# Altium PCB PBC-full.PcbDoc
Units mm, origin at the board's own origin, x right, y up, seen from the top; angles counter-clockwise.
Board outline 80.01 x 65.41 mm, 2 copper layers (Top Layer, Bottom Layer); 75 components, 86 nets, 316 pads, 108 vias.
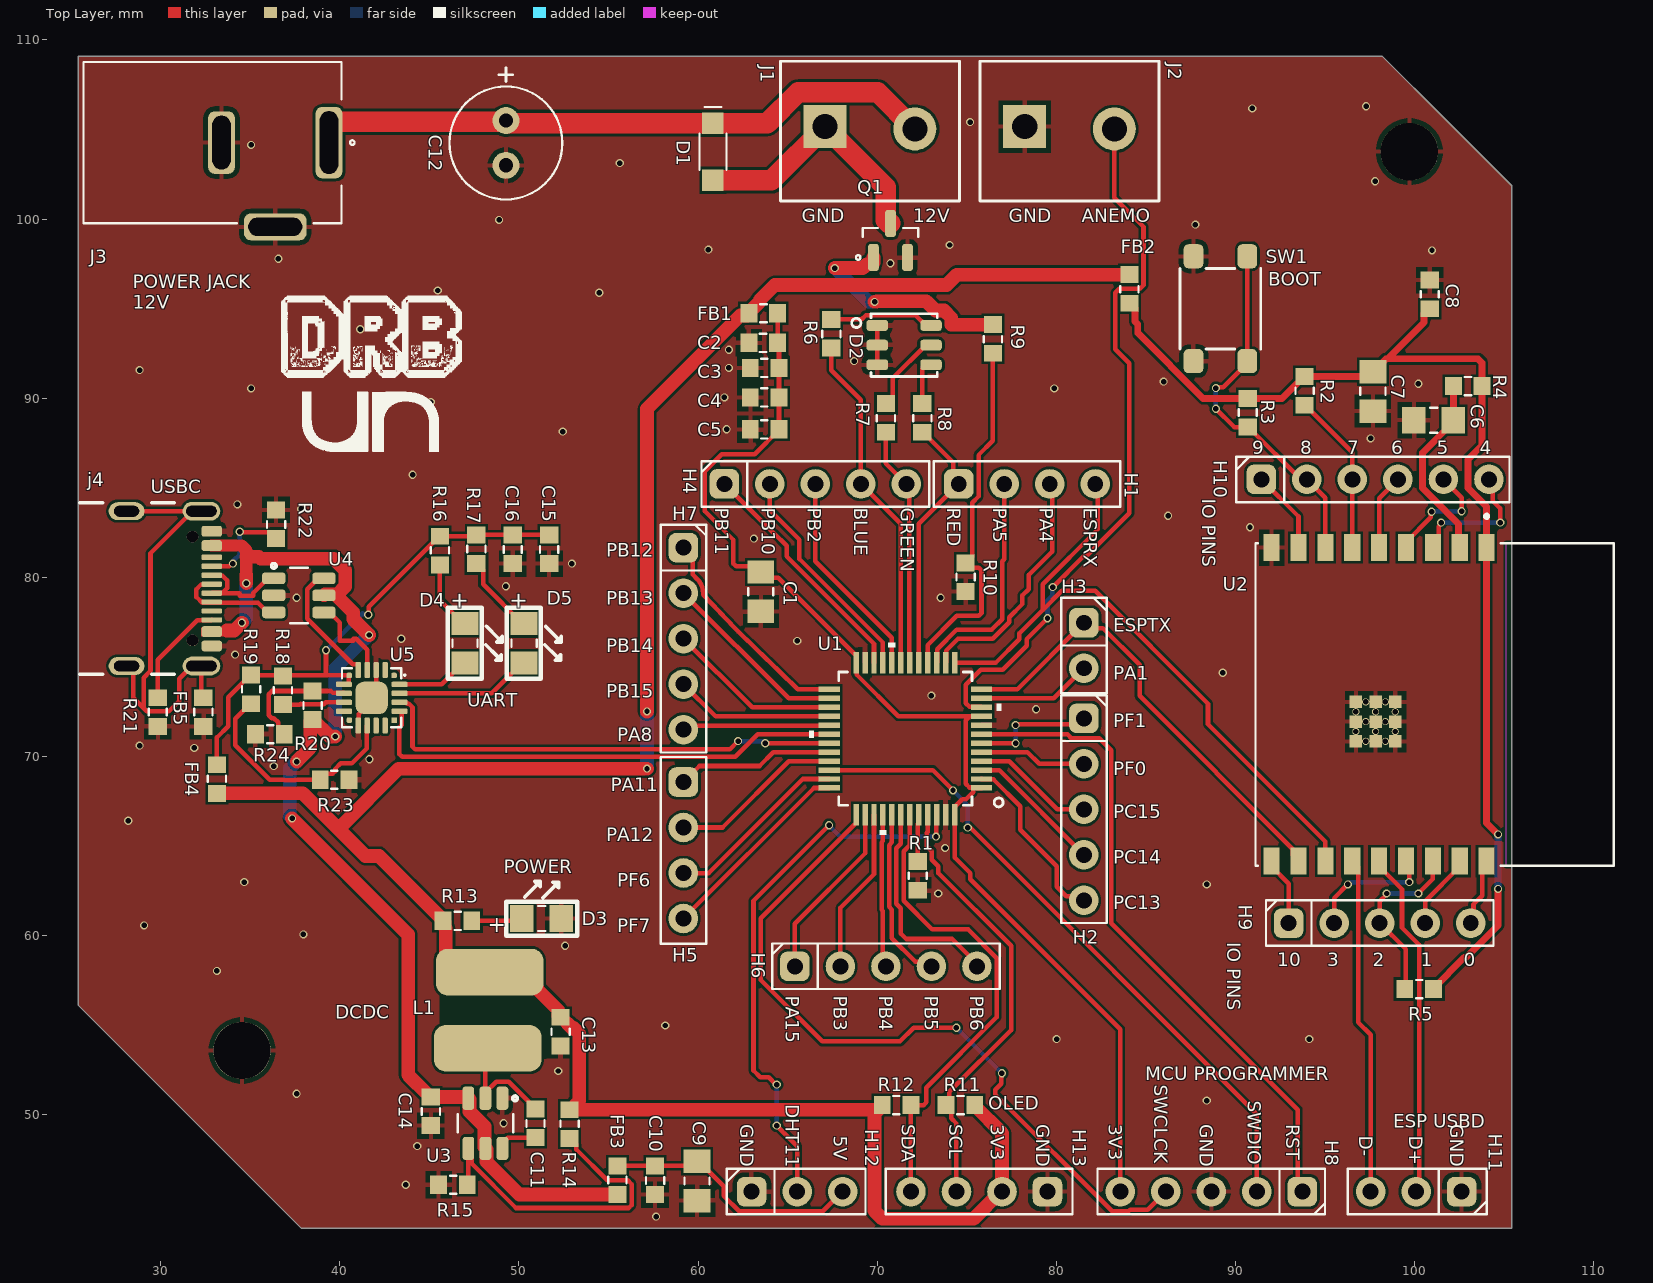
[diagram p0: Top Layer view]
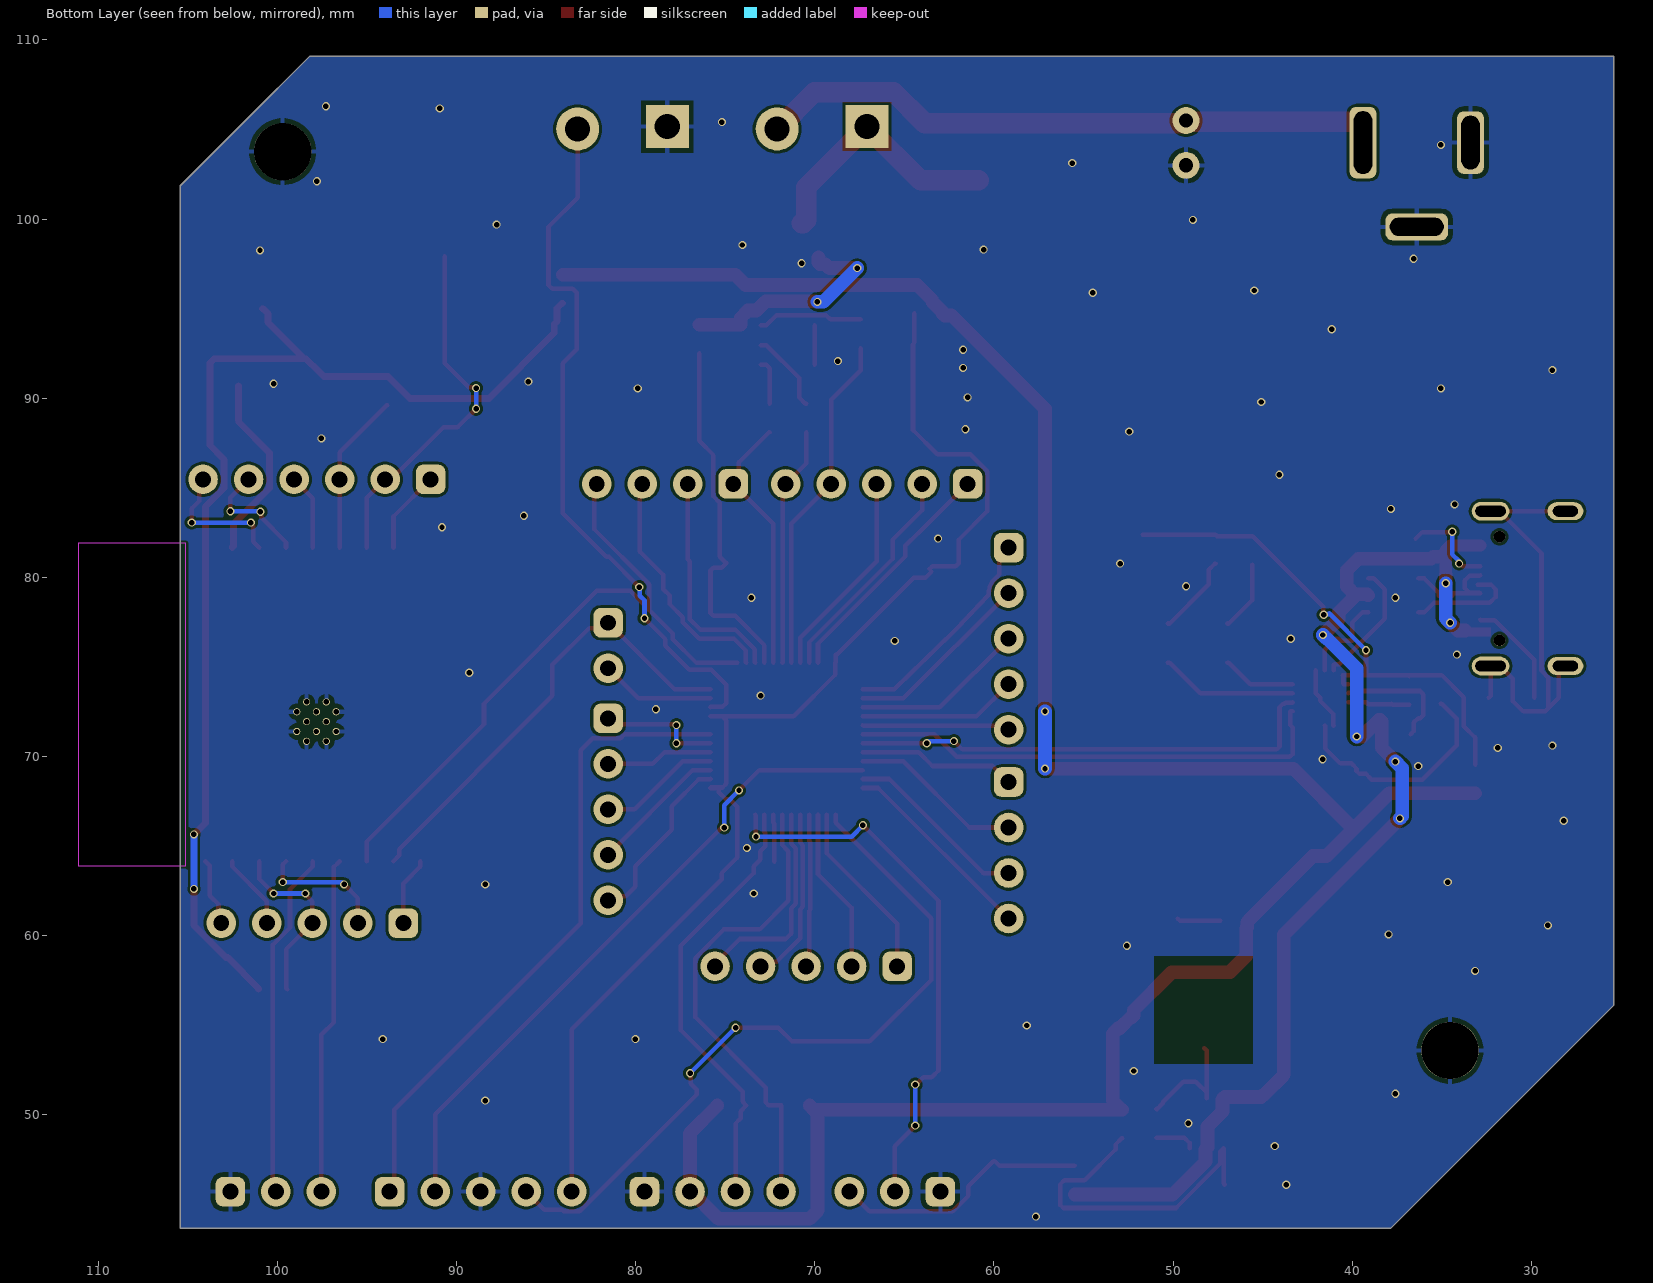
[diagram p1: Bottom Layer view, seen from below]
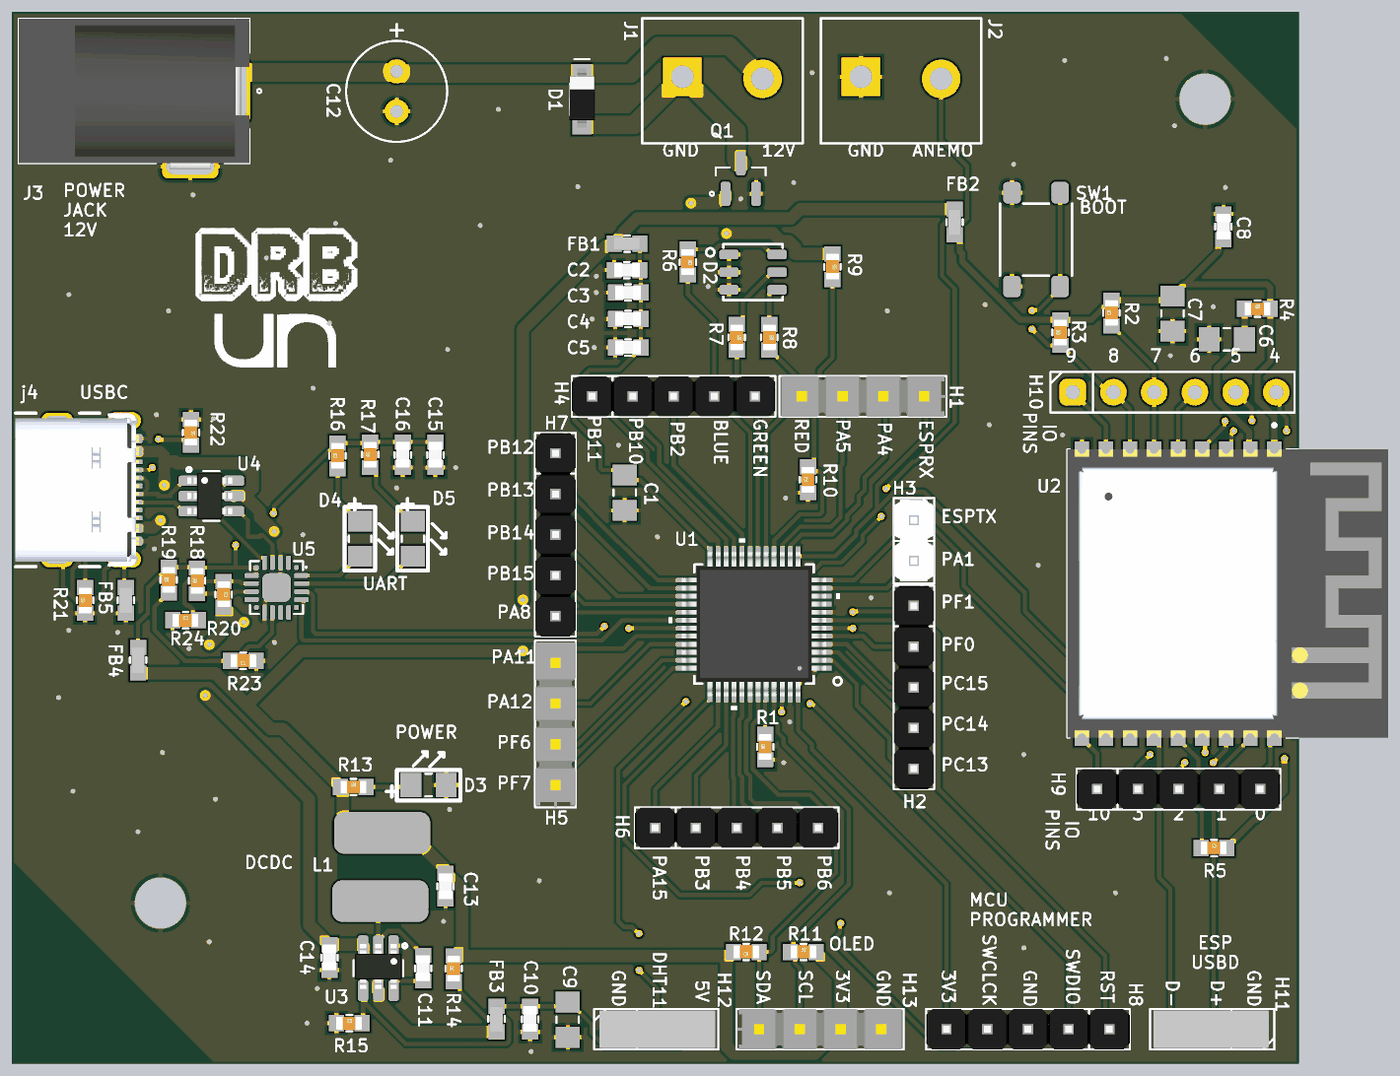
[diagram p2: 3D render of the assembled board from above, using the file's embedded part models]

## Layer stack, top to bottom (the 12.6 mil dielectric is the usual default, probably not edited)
Top Solder: solder mask 0.0102, Solder Resist, Dk 3.5
Top Layer: signal copper 0.0356
Dielectric 1: dielectric 0.32, FR-4, Dk 4.8
Bottom Layer: signal copper 0.0356
Bottom Solder: solder mask 0.0102, Solder Resist, Dk 3.5

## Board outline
37.846,43.688 25.4,56.134 25.4,109.093 98.171,109.093 101.727,105.537 105.41,101.854 105.41,43.688

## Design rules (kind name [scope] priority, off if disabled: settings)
Clearance [All] p1: gap=0.152 ignorepadtopadclearanceinfootprint=FALSE
DiffPairsRouting DiffPairsRouting_USB [InDifferentialPairClass('USB_2.0_MCU') and InDifferentialPairClass('USB_2.0_ESP')] p1: maxlimit=0.152 minlimit=0.152 mostfreqgap=0.152 toplayer_minwidth=0.279 toplayer_maxwidth=0.787 toplayer_prefwidth=0.787 bottomlayer_minwidth=0.279 bottomlayer_maxwidth=0.787 bottomlayer_prefwidth=0.787 maxuncoupledlength=12.7
HoleSize [All] p1: absolutevalues=TRUE maxlimit=25.4 minlimit=0.254 maxpercent=80.000 minpercent=20.000
MatchedLengths [InDifferentialPairClass('USB_2.0_MCU') and InDifferentialPairClass('USB_2.0_ESP')] p1: tolerance=1.27 checknetsindiffpair=TRUE checkdiffpairvsdiffpair=FALSE checkxsignals=FALSE checkothers=FALSE
MinimumSolderMaskSliver [All] p1: minsoldermaskwidth=0.102
PolygonConnect PolygonConnect_via [IsVia] p1: connectstyle=Direct reliefconductorwidth=0.254 reliefentries=4 polygonreliefangle="90 Angle" airgapwidth=0.254
PolygonConnect [All] p2: connectstyle=Relief reliefconductorwidth=0.254 reliefentries=4 polygonreliefangle="90 Angle" airgapwidth=0.254
RoutingVias [All] p1: holewidth=0.305 width=0.457 viastyle="Through Hole" minholewidth=0.305 minwidth=0.457 maxholewidth=25.4 maxwidth=25.4
SilkToSilkClearance [All] p1: silktosilkclearance=0.025
SilkToSolderMaskClearance [IsPad] p1: minsilkscreentomaskgap=0.025 clearancetoexposedcopper=TRUE
SolderMaskExpansion [All] p1: expansion=0.102 istentingtop=FALSE
SupplyNets "Schematic Supply Nets_6" [InNet('3V3_ESP32')] p1: voltage=0.000
SupplyNets "Schematic Supply Nets_5" [InNet('3V3_CP')] p2: voltage=0.000
SupplyNets "Schematic Supply Nets_4" [InNet('VUSB')] p3: voltage=0.000
SupplyNets "Schematic Supply Nets_3" [InNet('3V3_MCU')] p4: voltage=0.000
SupplyNets "Schematic Supply Nets_2" [InNet('3V3')] p5: voltage=0.000
SupplyNets "Schematic Supply Nets_1" [InNet('GND')] p6: voltage=0.000
SupplyNets "Schematic Supply Nets" [InNet('12V')] p7: voltage=0.000
Width Width_2A [InNetClass('12V_2A')] p1: maxlimit=1.143 minlimit=0.254 preferedwidth=1.143
Width Width_1A [InNetClass('5V_1A')] p2: maxlimit=0.762 minlimit=0.254 preferedwidth=0.762
Width Width_3V3_1A [InNet('3V3')] p3: maxlimit=0.762 minlimit=0.254 preferedwidth=0.762
Width Width_0.5A [InNet('3V3_ESP32')] p4: maxlimit=0.508 minlimit=0.381 preferedwidth=0.508
Width [All] p5: maxlimit=1.524 minlimit=0.152 preferedwidth=0.254
25 further rules are at their usual default settings.

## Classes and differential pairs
component class 300: C11 C12 C13 C14 C15 C16 D3 D4 D5 FB4 FB5 J3 j4 L1 R13 R14 R15 R16 R17 R18 R19 R20 R21 R22 R23 R24 U3 U4 U5
component class 100: C6 C7 C8 FB2 H9 H10 H11 R2 R3 R4 R5 SW1 U2
component class 000: C1 C2 C3 C4 C5 FB1 H1 H2 H3 H4 H5 H6 H7 H8 R1 U1
differential pair class USB_2.0_MCU: DATA USB_D
differential pair class USB_2.0_ESP: ESP_USBD
net class 12V_2A: 12V NetD1_2
net class 5V_1A: 3V3 NetC11_1 NetC11_2 VUSB
component class 200: C9 C10 D1 D2 FB3 H12 H13 J1 J2 Q1 R6 R7 R8 R9 R10 R11 R12 SDA
differential pair USB_D: +USB_D_P -USB_D_N
differential pair ESP_USBD: +ESP_USBD_P -ESP_USBD_N
differential pair DATA: +DATA_P -DATA_N

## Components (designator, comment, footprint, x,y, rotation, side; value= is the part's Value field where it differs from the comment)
C1 "10uF 25V" 0805_cap 63.5,79.205 r270 top value=10uF
C2 "0.1uF 50V" 0603_cap 63.64,93.091 r180 top value=0.1uF
C3 "0.1uF 50V" 0603_cap 63.716,91.694 r180 top value=0.1uF
C4 "0.1uF 50V" 0603_cap 63.716,90.043 r180 top value=0.1uF
C5 "0.1uF 50V" 0603_cap 63.716,88.265 r180 top value=0.1uF
C6 "10uF 25V" 0805_cap 101.049,88.773 r180 top value=10uF
C7 "10uF 25V" 0805_cap 97.663,90.381 r270 top value=10uF
C8 "0.1uF 50V" 0603_cap 100.838,95.796 r90 top value=0.1uF
C9 "10uF 25V" 0805_cap 59.944,46.312 r270 top value=10uF
C10 "0.1uF 50V" 0603_cap 57.6,46.355 r270 top value=0.1uF
C11 "0.1uF 50V" 0603_cap 50.927,49.53 r270 top value=0.1uF
C12 "100uF 35V" CAP_TH_2.5MM_6.3*12MM 49.276,104.247 r270 top value=100uF
C13 "22uF 10V" 0603_cap 52.324,54.648 r270 top value=22uF
C14 "10uF 10V" 0603_cap 45.085,50.203 r270 top value=10uF
C15 "10uF 10V" 0603_cap 51.689,81.572 r270 top value=10uF
C16 "0.1uF 50V" 0603_cap 49.657,81.572 r270 top value=0.1uF
D1 "40V 1A" SOD_123 60.833,103.759 r270 top
D2 "RGB" RGB_NS_3.5X3.7 71.501,92.964 r0 top
D3 "2.9V" 0805_LED 51.265,60.96 r0 top
D4 "2.9V" 0805_LED 46.99,76.327 r270 top
D5 "2V" 0805_LED 50.292,76.327 r270 top
FB1 "60OHM 2A" 0603_fb 63.64,94.742 r0 top value="60 OHM"
FB2 "60OHM 2A" 0603_fb 84.074,96.101 r270 top value="60 OHM"
FB3 "60OHM 2A" 0603_fb 55.499,46.355 r90 top value="60 OHM"
FB4 "60OHM 2A" 0603_fb 33.147,68.745 r90 top value="60 OHM"
FB5 "60OHM 2A" 0603_fb 32.385,72.479 r90 top value="60 OHM"
H1 "4x1" H_4x1_TH_2.54mm 78.359,85.217 r0 top
H2 "5x1" H_5x1_TH_100mil 81.534,67.056 r270 top
H3 "2x1" H_2x1_TH_100mil 81.534,76.2 r270 top
H4 "5x1" H_5x1_TH_100mil 66.548,85.217 r0 top
H5 "4x1" H_4x1_TH_2.54mm 59.182,64.77 r270 top
H6 "5x1" H_5x1_TH_100mil 70.485,58.293 r0 top
H7 "5x1" H_5x1_TH_100mil 59.182,76.581 r270 top
H8 "5x1" H_5x1_TH_100mil 88.646,45.72 r180 top
H9 "5x1" H_5x1_TH_100mil 98.044,60.706 r0 top
H10 "6x1" H_6x1_TH_100mil 97.79,85.471 r0 top
H11 "3x1" H_3X1_TH_100mil 100.076,45.72 r180 top
H12 "3x1" H_3X1_TH_100mil 65.532,45.72 r0 top
H13 "4x1" H_4x1_TH_2.54mm 75.692,45.72 r180 top
J1 "Connector 2pos" CON_2x1_TH_5MM 69.596,104.902 r0 top
J2 "Connector 2pos" CON_2x1_TH_5MM 80.732,104.902 r0 top
J3 "PWR JACK 2.1mm" CON_POWER_BARREL_2.1MM_3CONN 36.401,104.267 r270 top
j4 "USB C" CON_USB_C_16P_RA 30.48,79.375 r270 top
L1 "2.2uH 4A" Ind_5.8*5.2_NS 48.313,55.846 r90 top value=2.2uH
Q1 "N CH" SOT_23_3 70.739,98.806 r90 top
R1 "10k 1/10W" 0603_res 72.263,63.335 r90 top value=10k
R2 "1k 1/10W" 0603_res 93.853,90.411 r90 top value=1k
R3 "1k 1/10W" 0603_res 90.678,89.192 r90 top value=1k
R4 "1k 1/10W" 0603_res 102.959,90.678 r0 top value=1k
R5 "1k 1/10W" 0603_res 100.241,57.023 r0 top value=1k
R6 "100R 1/10W" 0603_res 67.437,93.599 r270 top value=100R
R7 "100R 1/10W" 0603_res 70.485,88.9 r270 top value=100R
R8 "100R 1/10W" 0603_res 72.517,88.9 r270 top value=100R
R9 "10k 1/10W" 0603_res 76.454,93.307 r270 top value=10k
R10 "10k 1/10W" 0603_res 74.93,80.01 r90 top value=10k
R11 "10k 1/10W" 0603_res 74.638,50.546 r0 top value=10k
R12 "10k 1/10W" 0603_res 71.082,50.546 r180 top value=10k
R13 "84R5 1/10W" 0603_res 46.571,60.833 r0 top value=84R5
R14 "33k2 1/10W" 0603_res 52.832,49.492 r90 top value=33k2
R15 "10k 1/10W" 0603_res 46.317,46.101 r0 top value=10k
R16 "84R5 1/10W" 0603_res 45.593,81.496 r90 top value=84R5
R17 "150R 1/10W" 0603_res 47.625,81.572 r90 top value=150R
R18 "1k 1/10W" 0603_res 36.83,73.698 r90 top value=1k
R19 "10k 1/10W" 0603_res 35.052,73.749 r90 top value=10k
R20 "33k2 1/10W" 0603_res 38.481,72.86 r270 top value=33k2
R21 "4k7 1/10W" 0603_res 29.845,72.479 r90 top value=4k7
R22 "4k7 1/10W" 0603_res 36.449,82.969 r270 top value=4k7
R23 "10k 1/10W" 0603_res 39.713,68.707 r180 top value=10k
R24 "54k9 1/10W" 0603_res 36.106,71.247 r0 top value=54k9
SW1 "Sw" Sw_PUSH_4.5x4.5x5mm 89.154,94.996 r90 top
U1 "STM32F030C8T6TR" LQFP48_7x7mm 71.569,70.997 r180 top
U2 "ESP32-C3-WROOM-02-N4" ESP32-C3-WROOM-02-N4 98.013,72.911 r270 top
U3 "TPS564201DDCR" SOT_23_6 48.133,49.53 r270 top
U4 "USBLC6-2SC6" SOT_23_6 37.719,78.994 r0 top
U5 "CP2102N-A02-GQFN20R" WFQFN_20_EP_3X3MM 41.783,73.279 r270 top

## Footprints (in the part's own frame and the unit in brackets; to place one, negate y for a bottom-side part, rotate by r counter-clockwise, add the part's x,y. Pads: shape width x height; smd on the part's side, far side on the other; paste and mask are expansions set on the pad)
0603_cap [mil]
  rect 37x40 smd: 1(-31.5,0) 2(31.5,0)
  silkscreen extent -7,-20 8,20, body extent -31,-17 31,17, height 34
0603_fb [mil]
  rect 37x40 smd: 1(-31.5,0) 2(31.5,0)
  silkscreen extent -6,-20 8,20, body extent -32,-16 31,16, height 32
0603_res [mil] "1608 Metric / 20190225 / C-A.Serna.A"
  rect 37x40 smd: 1(-31.5,0) 2(31.5,0)
  silkscreen extent -7,-20 8,20, body extent -31,-16 32,16, height 12
0805_cap [mm]
  rect 1.3x1.5 smd: 1(-1.1,0) 2(1.1,0)
  silkscreen extent -0.2,-0.7 0.2,0.7, body extent -1.13,-0.7 1.07,0.7, height 1
0805_LED [mm]
  rect 1.3x1.5 smd: 1(-1.1,0) 2(1.1,0)
  silkscreen extent -1.98,-0.97 1.98,2.07, body extent -1,-0.62 1,0.63, height 1.1
CAP_TH_2.5MM_6.3*12MM [mm]
  round 1.5 hole 0.8: 1(-1.25,0) 2(1.25,0)
  silkscreen extent -4.19,-3.15 3.15,3.15, body extent -3.15,-3.15 3.15,3.15, height 12
CON_2x1_TH_5MM [mm]
  rect 2.4x2.4 hole 1.4: 1(-2.5,0.254)
  round 2.4 hole 1.4: 2(2.5,0.127)
  silkscreen extent -5,-3.9 5,3.9, body extent -5,-3.9 5,3.9, height 10.2
CON_POWER_BARREL_2.1MM_3CONN [mm]
  rrect50% 4x1.5 hole 1.016 slot 3.5 at 0 deg: 1(0,3)
  rrect50% 3.5x1.5 hole 1.016 slot 3 at 0 deg: 2(0,-3)
  rrect50% 1.5x3.5 hole 1.016 slot 3 at 90 deg: 3(4.7,0)
  silkscreen extent -4.5,-10.7 4.5,4.43, body extent -4.5,-10.7 4.9,3.7, height 11
CON_USB_C_16P_RA [mm]
  oval 1.05x2.1 hole 0.6 slot 1.7 at 90 deg: 0(-4.32,1.803) 0(4.32,1.803)
  oval 1x2 hole 0.6 slot 1.4 at 90 deg: 0(-4.32,-2.377) 0(4.32,-2.377)
  rrect50% 0.6x1.15 smd mask+0.046: A1/B12(-3.2,2.378) A4/B9(-2.4,2.378) B1/A12(3.2,2.378) B4/A9(2.4,2.378)
  rrect50% 0.3x1.15 smd mask+0.046: A5(-1.25,2.378) A6(-0.25,2.378) A7(0.25,2.378) A8(1.25,2.378) B5(1.75,2.378) B6(0.75,2.378) B7(-0.75,2.378) B8(-1.75,2.378)
  round 0.65 hole 0.65 unplated mask+0.046: ""(-2.89,1.303) ""(2.89,1.303)
  silkscreen extent -4.79,-4.98 4.79,0.27, body extent -4.79,-4.98 4.79,2.73, height 3.31
ESP32-C3-WROOM-02-N4 [mm]
  rect 1.5x0.9 smd: 1(-8.75,6) 2(-8.75,4.5) 3(-8.75,3) 4(-8.75,1.5) 5(-8.75,0) 6(-8.75,-1.5) 7(-8.75,-3) 8(-8.75,-4.5) 9(-8.75,-6) 10(8.75,-6) 11(8.75,-4.5) 12(8.75,-3) 13(8.75,-1.5) 14(8.75,0) 15(8.75,1.5) 16(8.75,3) 17(8.75,4.5) 18(8.75,6)
  rect 0.7x0.7 smd: 19(-0.14,0.9) 19(-0.14,-0.2) 19(-0.14,-1.3) 19(0.96,0.9) 19(0.96,-0.2) 19(0.96,-1.3) 19(2.06,-0.2) 19(2.06,0.9) 19(2.06,-1.3)
  round 0.4 hole 0.3 mask+0: 19(-0.14,0.35) 19(-0.14,-0.75) 19(0.41,0.9) 19(0.41,-0.2) 19(0.41,-1.3) 19(0.96,0.35) 19(0.96,-0.75) 19(1.51,0.9) 19(1.51,-0.2) 19(1.51,-1.3) 19(2.06,-0.75) 19(2.06,0.35)
  Keep-Out Layer region: 9,7.1 -9,7.1 -9,13.1 9,13.1
  Keep-Out Layer region: 9,7.1 -9,7.1 -9,13.1 9,13.1
  silkscreen extent -10.6,-6.9 9,13.1, body extent -9,-6.9 9,13.1, height 3.35
H_2x1_TH_100mil [mil]
  rrect50% 65x65 hole 35: 1(-50,0)
  round 65 hole 35: 2(50,0)
  silkscreen extent -105,-50 105,50, body extent -101,-49 99,49, height 339
H_3X1_TH_100mil [mil]
  rrect50% 65x65 hole 35: 1(-100,0)
  round 65 hole 35: 2(0,0) 3(100,0)
  silkscreen extent -155,-50 150,50, body extent -142,-46 142,46, height 320
H_4x1_TH_2.54mm [mil]
  rrect50% 65x65 hole 35: 1(-150,0)
  round 65 hole 35: 2(-50,0) 3(50,0) 4(150,0)
  silkscreen extent -205,-50 205,50, body extent -200,-50 205,50, height 420
H_5x1_TH_100mil [mil]
  rrect50% 65x65 hole 35: 1(-200,0)
  round 65 hole 35: 2(-100,0) 3(0,0) 4(100,0) 5(200,0)
  silkscreen extent -250,-50 250,50, body extent -250,-49 250,49, height 335
H_6x1_TH_100mil [mil]
  rrect50% 65x65 hole 35: 1(-250,0)
  round 65 hole 35: 2(-150,0) 3(-50,0) 4(50,0) 5(150,0) 6(250,0)
  silkscreen extent -305,-50 295,50
Ind_5.8*5.2_NS [mm]
  rrect50% 2.6x6 smd: 1(-2.125,0.053) 2(2.125,-0.053)
  body extent -3,-2.75 3,2.75, height 4.5
LQFP48_7x7mm [mm]
  rect 1.194x0.305 smd paste+0 mask+0.046: 1(-4.25,2.75) 2(-4.25,2.25) 3(-4.25,1.75) 4(-4.25,1.25) 5(-4.25,0.75) 6(-4.25,0.25) 7(-4.25,-0.25) 8(-4.25,-0.75) 9(-4.25,-1.25) 10(-4.25,-1.75) 11(-4.25,-2.25) 12(-4.25,-2.75) 25(4.25,-2.75) 26(4.25,-2.25) 27(4.25,-1.75) 28(4.25,-1.25) 29(4.25,-0.75) 30(4.25,-0.25) 31(4.25,0.25) 32(4.25,0.75) 33(4.25,1.25) 34(4.25,1.75) 35(4.25,2.25) 36(4.25,2.75)
  rect 0.305x1.194 smd paste+0 mask+0.046: 13(-2.75,-4.25) 14(-2.25,-4.25) 15(-1.75,-4.25) 16(-1.25,-4.25) 17(-0.75,-4.25) 18(-0.25,-4.25) 19(0.25,-4.25) 20(0.75,-4.25) 21(1.25,-4.25) 22(1.75,-4.25) 23(2.25,-4.25) 24(2.75,-4.25) 37(2.75,4.25) 38(2.25,4.25) 39(1.75,4.25) 40(1.25,4.25) 41(0.75,4.25) 42(0.25,4.25) 43(-0.25,4.25) 44(-0.75,4.25) 45(-1.25,4.25) 46(-1.75,4.25) 47(-2.25,4.25) 48(-2.75,4.25)
  silkscreen extent -5.46,-5.35 5.35,5.35, body extent -4.5,-4.5 4.5,4.5, height 1.6
RGB_NS_3.5X3.7 [mm]
  rrect50% 1.2x0.6 smd: 1(-1.5,1.1) 2(-1.5,0) 3(-1.5,-1.1) 4(1.5,-1.1) 5(1.5,0) 6(1.5,1.1)
  silkscreen extent -2.92,-1.75 1.85,1.75, body extent -1.85,-1.74 1.85,1.75, height 1
SOD_123 [mm]
  rect 1.2x1.2 smd: 1(-1.6,0) 2(1.6,0)
  silkscreen extent -2.5,-0.75 1,0.75, body extent -1.93,-0.8 1.77,0.8, height 1.28
SOT_23_3 [mm]
  rrect50% 1.5x0.6 smd: 1(-0.95,0.95) 2(-0.95,-0.95) 3(0.95,0)
  silkscreen extent -1.07,-1.55 0.7,1.92, body extent -0.7,-1.52 0.7,1.53, height 1.12
SOT_23_6 [mm]
  rrect50% 1.3x0.65 smd mask+0.064: 1(-1.4,0.95) 2(-1.4,0) 3(-1.4,-0.95) 4(1.4,-0.95) 5(1.4,0) 6(1.4,0.95)
  silkscreen extent -1.52,-1.55 0.5,1.78, body extent -1.5,-1.45 1.3,1.45, height 1.45
Sw_PUSH_4.5x4.5x5mm [mm]
  rrect50% 1.35x1.1 smd: 1(-2.925,1.5) 1(2.925,1.5) 2(-2.925,-1.5) 2(2.925,-1.5)
  silkscreen extent -2.25,-2.25 2.25,2.25, body extent -2.25,-2.25 2.25,2.25, height 5
WFQFN_20_EP_3X3MM [mm]
  rrect50% 0.3x0.3 smd mask+0.046: 1(-1.25,1.25) 6(-1.25,-1.25) 11(1.25,-1.25)
  rrect50% 0.9x0.3 smd mask+0.046: 2(-1.55,0.75) 3(-1.55,0.25) 4(-1.55,-0.25) 5(-1.55,-0.75) 12(1.55,-0.75) 13(1.55,-0.25) 14(1.55,0.25) 15(1.55,0.75)
  rrect50% 0.3x0.9 smd mask+0.046: 7(-0.75,-1.55) 8(-0.25,-1.55) 9(0.25,-1.55) 10(0.75,-1.55) 17(0.75,1.55) 18(0.25,1.55) 19(-0.25,1.55) 20(-0.75,1.55)
  rect 0.3x0.3 smd mask+0.046: 16(1.25,1.25)
  rrect50% 1.8x1.8 smd mask+0.046: 21(0,0)
  silkscreen extent -1.65,-1.65 1.65,1.9, body extent -1.5,-1.5 1.5,1.5, height 0.8

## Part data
C1 C6 C7 C9: library part Cap_10uF_0805_25V_, "25V 10uF X5R ±10% 0805 Multilayer Ceramic Capacitors MLCC - SMD/SMT ROHS", Manufacturer="Samsung Electro-Mechanics", Manufacturer Part Number=CL21A106KAYNNNE, Supplier Part Number 1=C15850
C2 C3 C4 C5 C8 C10 C11 C16: library part Cap_0.1uF_0603_50V, "50V 100nF Y5V -20%~+80% 0603 Multilayer Ceramic Capacitors MLCC - SMD/SMT ROHS", Manufacturer="Walsin Tech Corp", Manufacturer Part Number=0603F104Z500CT, Supplier Part Number 1=C83060
C12: library part Cap_100uF_ALU_TH_35V, "100uF 35V ±20% Plugin,D6.3xL12mm Aluminum Electrolytic Capacitors - Leaded ROHS", Manufacturer=HRK, Manufacturer Part Number="35V100uF CD110", Supplier Part Number 1=C2960381
C13: library part Cap_22uF_0603_10V, "10V 22uF X5R ±20% 0603 Multilayer Ceramic Capacitors MLCC - SMD/SMT ROHS", Manufacturer=HRE, Manufacturer Part Number=CGA0603X5R226M100JT, Supplier Part Number 1=C6119863
C14 C15: library part Cap_10uF_0603_10V, "10V 10uF X5R ±10% 0603 Multilayer Ceramic Capacitors MLCC - SMD/SMT ROHS", Manufacturer=CCTC, Manufacturer Part Number=TCC0603X5R106K100CT, Supplier Part Number 1=C380314
D1: library part D_Schottky_40V_1A_SOD_123F, "DIODE SCHOTTKY 40V 1A SOD123F", Manufacturer="Shanghai Prisemi Elec", Manufacturer Part Number=PSBD1DF40V1H, Supplier Part Number 1=C110730
D2: library part LED_RGB_3535_SMD, "-30℃~+85℃ RGB 110° 3535(mm) Light Emitting Diodes (LED) ROHS", Manufacturer="Foshan NationStar Optoelectronics", Manufacturer Part Number=RS-3535MWAM, Supplier Part Number 1=C842778
D3 D4: library part LED_0805_Green, "LED GREEN CLEAR 0805 SMD", Manufacturer=XINGLIGHT, Manufacturer Part Number=XL-2012UGC, Supplier Part Number 1=C965815
D5: library part LED_0805_RED, "LED RED CLEAR 0805 SMD", Manufacturer=XINGLIGHT, Manufacturer Part Number=XL-2012SURC, Supplier Part Number 1=C965812
FB1 FB2 FB3 FB4 FB5: library part FB_60_0603_2A, "2A 1 100mΩ 60Ω@100MHz ±25% 0603 Ferrite Beads ROHS", Manufacturer=TAI-TECH, Manufacturer Part Number=HCB1608KF-600T20, Supplier Part Number 1=C369516
H1 H5 H13: library part H_Male_4x1_TH_100mil, "H_Male_4x1_TH_100mil"
H2 H4 H6 H7 H8 H9: library part H_Male_5x1_TH_100mil, "H_Male_5x1_TH_100mil"
H3: library part H_Male_2x1_TH_100mil, "H_Male_2x1_TH_100mil"
H10: library part H_Male_6x1_TH_100mil, "H_Male_6x1_TH_100mil"
H11 H12: library part H_Male_3x1_TH_100mil, "H_Male_3x1_TH_100mil"
J1 J2: library part Con_2x1_TH_5mm, "2POS 5MM", Manufacturer=JILN, Manufacturer Part Number=JL126-50002G01, Supplier Part Number 1=C394556
J3: library part Con_Power_Jack_2.1mm_3pins, "CONN PWR JACK 2X5.5MM SOLDER", Manufacturer=HCTL, Manufacturer Part Number=HC-DC-005-2.0T, Supplier Part Number 1=C3010533
j4: library part CON_USB_TYPEC_16P, "3A USB 3.1 1 Surface Mount 16P Female -40℃~+85℃ Type-C SMD USB Connectors ROHS", Manufacturer="SHOU HAN", Manufacturer Part Number=TYPE-C-3.1-16PIN, Supplier Part Number 1=C7507405
L1: library part Inductor_2.2uH_4A_5.8*5.2mm, "4A 2.2uH ±20% 22.1mΩ SMD,5.8x5.2mm Inductors (SMD) ROHS", Manufacturer="SHOU HAN", Manufacturer Part Number=CY54-2.2UH, Supplier Part Number 1=C2929427
Q1: library part Q_NFET_20V_3.2A_SOT23, "MOSFET N-CH 20V SOT23", Manufacturer=Doeshare, Manufacturer Part Number=DN2302S, Supplier Part Number 1=C2931750
R1 R9 R10 R11 R12 R15 R19 R23: library part Res_10k_0603_1/10W, "RES SMD 10k OHM 5% 1/10W 0603", Manufacturer=FOJAN, Manufacturer Part Number=FRC0603J103TS, Supplier Part Number 1=C2930027
R2 R3 R4 R5 R18: library part Res_1k_0603_1/10W, "RES SMD 1k OHM 5% 1/10W 0603", Manufacturer=FOJAN, Manufacturer Part Number="FRC0603J102 TS", Supplier Part Number 1=C2907113
R6 R7 R8: library part Res_100R_0603_1/10W, "RES SMD 100R OHM 5% 1/10W 0603", Manufacturer=FOJAN, Manufacturer Part Number="FRC0603J101 TS", Supplier Part Number 1=C2907089
R13 R16: library part Res_84R5_0603_1/10W, "100mW Thick Film Resistor 50V ±100ppm/℃ ±1% 84.5Ω 0603 Chip Resistor - Surface Mount ROHS", Manufacturer="LIZ Elec", Manufacturer Part Number=CR0603FA84R5G, Supplier Part Number 1=C101216
R14 R20: library part Res_33k2_0603_1/10W, "100mW Thick Film Resistor 75V ±100ppm/℃ ±1% 33.2kΩ 0603 Chip Resistor - Surface Mount ROHS", Manufacturer=YAGEO, Manufacturer Part Number=RC0603FR-0733K2L, Supplier Part Number 1=C185338
R17: library part Res_150R_0603_1/10W, "100mW Thick Film Resistor 75V ±100ppm/℃ ±1% 150Ω 0603 Chip Resistor - Surface Mount ROHS", Manufacturer=RALEC, Manufacturer Part Number=RTT031500FTP, Supplier Part Number 1=C103302
R21 R22: library part Res_4k7_0603_1/10W, "100mW Thick Film Resistor 75V ±1% 4.7kΩ 0603 Chip Resistor - Surface Mount ROHS", Manufacturer=VO, Manufacturer Part Number=SCR0603F4K7, Supplier Part Number 1=C3016318
R24: library part Res_54k9_0603_1/10W, "100mW Thick Film Resistor 75V ±100ppm/℃ ±1% 54.9kΩ 0603 Chip Resistor - Surface Mount ROHS", Manufacturer=YAGEO, Manufacturer Part Number=RC0603FR-0754K9L, Supplier Part Number 1=C185321
SW1: library part Sw_PUSH_4.5x4.5x5.0xmm, "SWITCH TACTILE SPST-NO 0.05A 12V", Manufacturer=BZCN, Manufacturer Part Number=TSC015A05026A, Supplier Part Number 1=C2888509
U1: library part IC_STM32F030C8T6TR_LQFP48_7x7MM, "IC MCU 32BIT 64KB FLASH 48LQFP", Manufacturer=STMicroelectronics, Supplier Part Number 1=C23922
U2: library part MCU_ESP32-C3-WROOM-02-N4, "RF TXRX MOD BT WIFI PCB TH SMD", Manufacturer="Espressif Systems", Supplier Part Number 1=C2934560
U3: library part DCDC_SW_BUCK_4A_SOT23-6, "IC REG BUCK ADJ 4A SOT23", Manufacturer="Texas Instruments", Supplier Part Number 1=C464812
U4: library part TVS_5.25V_2CH_SOT_23_6, "TVS DIODE 5.25V 17V SOT23-6", Manufacturer=STMicroelectronics, Supplier Part Number 1=C7519
U5: library part IC_SGL_USB2UART-BRIDGE_20QFN, "IC USB TO UART BRIDGE QFN20", Manufacturer="Silicon Labs", Supplier Part Number 1=C969913

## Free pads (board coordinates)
  round 3.2 hole 3.2 mask+0: 1(34.544,53.594) 1(99.695,103.759)

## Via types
v1: diameter 0.457, hole 0.305, Top Layer to Bottom Layer, tented both sides, 68 vias
v2: diameter 0.457, hole 0.305, Top Layer to Bottom Layer, 40 vias

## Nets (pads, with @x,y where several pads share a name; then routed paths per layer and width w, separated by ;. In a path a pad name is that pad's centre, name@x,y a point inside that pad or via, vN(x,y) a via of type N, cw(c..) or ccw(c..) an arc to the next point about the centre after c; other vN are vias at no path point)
3V3: C13.1 FB1.1 FB2.1 FB4.1 H13.2 L1.2 R11.2 R12.2 R13.1 R14.2 | length 137.3
  Top Layer w0.762: FB4.1 37.943,67.945 39.926,65.961 ; C13.1 52.286,55.448 52.197,55.537 52.197,55.841 50.067,57.971 L1.2 46.822,57.971 45.924,58.87 45.924,60.414 45.86,60.478 45.86,60.744 R13.1 45.771,60.871 42.189,64.453 41.435,64.453 39.926,65.961 ; C13.1@52.362,55.448 52.959,54.851 53.053,54.851 53.365,54.539 53.365,50.787 R14.2@52.87,50.292 ; R14.2 R14.2@52.87,50.292 ; v2(57.15,69.329) 43.294,69.329 39.926,65.961 ; v2(57.15,72.517) 57.15,89.408 62.357,94.615 62.751,94.615 62.84,94.704 FB1.1 ; FB1.1@62.84,94.78 63.436,95.377 63.436,95.471 64.284,96.319 73.869,96.319 74.451,96.901 FB2.1 ; R11.2 75.438,50.508 76.962,48.984 H13.2 76.896,45.72 75.372,44.196 70.296,44.196 69.85,44.642 69.85,50.076 R12.2@70.282,50.508 ; R14.2@52.87,50.292 70.066,50.292 R12.2@70.282,50.508 ; R12.2@70.282,50.508 R12.2 R12.2@70.282,50.508
  Bottom Layer w0.762: v2(57.15,69.329) v2(57.15,72.517)
3V3_CP: C15.1 C16.1 FB4.2 R16.2 R17.2 R18.2 R19.2 U5.6 U5.7 | length 29
  Top Layer w0.254: FB4.2 33.147,71.068 33.769,71.69 33.769,73.304 35.014,74.549 R19.2 36.779,74.549 R18.2 36.861,74.529 39.116,74.529 ; v2(39.233,75.936) 39.233,74.646 39.116,74.529 ; U5.7 40.487,74.029 40.51,74.052 40.51,74.506 U5.6 39.116,74.529 ; v2(41.589,77.911) 41.628,77.95 41.628,78.369 45.555,82.296 R16.2 47.549,82.296 R17.2 C16.1 C15.1
  Bottom Layer w0.254: v2(39.233,75.936) 41.293,77.996 41.339,77.95 41.55,77.95 v2(41.589,77.911)
3V3_ESP32: C7.1 C8.1 FB2.2 R2.2 R3.2 R4.2 R5.2 U2.1 | length 64.9
  Top Layer w0.381: FB2.2 84.112,95.301 84.391,95.021 84.391,94.275 84.544,94.122 84.544,93.632 88.184,89.992 R3.2 92.596,89.992 93.815,91.211 R2.2 97.393,91.211 C7.1 98.384,92.202 98.484,92.202 ; C8.1 100.8,94.996 100.52,94.717 100.52,94.239 98.484,92.202 ; R5.2 101.041,57.061 102.761,58.781 102.852,58.781 104.648,60.578 v2(104.648,62.611) ; v2(104.648,65.659) 104.013,66.294 U2.1 104.013,83.946 102.972,84.987 102.972,86.589 103.759,87.376 R4.2 103.759,91.979 103.536,92.202 98.484,92.202
  Bottom Layer w0.381: v2(104.648,62.611) v2(104.648,65.659)
3V3_MCU: C1.1 C2.1 C3.1 C4.1 C5.1 FB1.2 H8.5 U1.1 U1.9 U1.24 U1.48 | length 67.6
  Top Layer w0.254: C1.1 63.817,79.988 64.482,79.988 68.753,75.717 68.794,75.717 68.819,75.691 U1.24 68.844,75.222 68.844,74.577 71.175,72.247 75.106,72.247 U1.9 ; C1.1@63.596,80.47 63.449,80.617 62.125,80.617 61.976,80.766 61.976,82.09 60.363,83.703 60.363,85.916 61.315,86.868 63.157,86.868 64.516,88.227 C5.1 C4.1 C3.1 64.516,93.015 C2.1 FB1.2 ; 75.106,72.179 74.943,72.015 74.943,68.479 75.149,68.272 75.349,68.272 75.794,68.272 U1.1 75.374,68.247 75.349,68.222 75.349,68.006 74.955,67.611 74.739,67.611 74.319,67.192 74.319,64.365 75.184,63.5 75.184,63.162 83.566,54.78 H8.5
12V: C12.1 D1.1 J1.2 J3.1 | length 35.4
  Top Layer w1.143: J3.1 39.401,105.25 39.579,105.429 49.208,105.429 C12.1 49.373,105.497 49.511,105.359 D1.1 63.875,105.359 65.596,107.08 70.025,107.08 72.076,105.029 J1.2
ADC_ANEMO: J2.2 U1.10 | length 39.9
  Top Layer w0.254: U1.10 75.794,72.772 75.149,72.772 74.943,72.979 74.943,74.015 75.768,74.841 77,74.841 78.338,76.179 78.338,76.56 v2(79.502,77.724) ; v2(79.8,79.458) 81.484,81.143 81.628,81.143 84.074,83.589 84.074,91.948 83.287,92.735 83.287,95.886 83.501,96.101 84.647,96.101 84.861,96.315 84.861,99.567 83.232,101.197 J2.2
  Bottom Layer w0.254: v2(79.502,77.724) 79.502,78.722 79.761,78.981 79.761,79.42 v2(79.8,79.458)
DATA_N: U4.6 U5.5 | length 7
  Top Layer w0.254: U4.6 38.794,79.944 38.19,79.34 38.19,77.698 40.736,75.152 41.01,75.152 41.033,75.129 U5.5
DATA_P: U4.4 U5.4 | length 5.2
  Top Layer w0.254: U4.4 39.444,78.044 40.008,77.48 40.008,76.455 40.77,76.455 40.77,76.569 40.919,76.569 41.529,75.959 41.533,75.955 U5.4
DHT11_PIN: H12.2 U1.46 | length 31
  Top Layer w0.254: v2(64.389,49.403) 65.532,48.26 H12.2 ; v2(64.389,51.689) 64.353,51.689 63.94,52.102 63.468,52.102 63.094,52.476 63.094,61.951 v2(67.31,66.167) ; v2(73.279,65.532) 73.299,65.552 73.299,66.727 U1.46
  Bottom Layer w0.254: v2(64.389,49.403) v2(64.389,51.689) ; v2(67.31,66.167) 67.945,65.532 v2(73.279,65.532)
ESP_EN: C6.1 R4.1 U2.2 | length 10.6
  Top Layer w0.381: R4.1 102.159,88.783 C6.1 102.149,88.673 100.432,86.956 100.432,84.987 102.436,82.983 102.436,81.738 U2.2
ESP_IO0: H9.5 U2.18 | length 3.8
  Top Layer w0.254: H9.5 103.279,60.861 103.279,61.75 103.759,62.23 103.759,63.907 U2.18
ESP_IO1: H9.4 U2.17 | length 4.3
  Top Layer w0.254: H9.4 100.584,61.932 102.513,63.861 U2.17
ESP_IO2: H9.3 R5.1 U2.16 | length 10
  Top Layer w0.254: v2(98.425,62.357) 98.425,62.302 98.044,61.921 H9.3 99.492,59.258 99.492,57.074 R5.1 ; v2(100.203,62.357) 101.013,63.167 U2.16
  Bottom Layer w0.254: v2(98.425,62.357) v2(100.203,62.357)
ESP_IO3: H9.2 U2.15 | length 7.2
  Top Layer w0.254: H9.2 95.504,62.103 v2(96.266,62.865) ; U2.15 99.695,63.979 v2(99.695,62.992)
  Bottom Layer w0.254: v2(96.266,62.865) 96.393,62.992 v2(99.695,62.992)
ESP_IO4: H10.6 U2.3 | length 7.6
  Top Layer w0.254: U2.3 101.336,81.984 101.336,82.866 101.473,83.003 v2(101.473,83.058) ; H10.6 104.359,85.252 104.359,84.264 104.775,83.848 v2(104.775,83.058)
  Bottom Layer w0.254: v2(101.473,83.058) v2(104.775,83.058)
ESP_IO5: H10.5 U2.4 | length 6.5
  Top Layer w0.254: U2.4 99.513,81.961 100.902,83.35 100.902,83.63 v2(100.941,83.669) ; H10.5 102.616,84.455 v2(102.616,83.693)
  Bottom Layer w0.254: v2(100.941,83.669) 100.953,83.681 102.604,83.681 v2(102.616,83.693)
ESP_IO6: H10.4 U2.5 | length 4.2
  Top Layer w0.254: U2.5 98.013,84.424 H10.4
ESP_IO7: H10.3 R2.1 U2.6 | length 9.1
  Top Layer w0.254: R2.1 93.891,89.611 96.52,86.982 H10.3 96.52,81.668 U2.6
ESP_IO8: H10.2 R3.1 SW1.2 U2.7 | length 20.4
  Top Layer w0.254: v2(88.9,89.408) 89.916,88.392 R3.1 ; v2(88.9,90.564) 88.939,90.603 89.311,90.603 90.654,91.946 90.654,92.071 SW1.2@90.654,97.921 ; R3.1@90.716,88.392 93.637,85.471 H10.2 95.013,84.438 U2.7
  Bottom Layer w0.254: v2(88.9,89.408) v2(88.9,90.564)
ESP_IO9: H10.1 U2.8 | length 4.7
  Top Layer w0.254: H10.1 93.513,83.398 U2.8
ESP_IO10: H9.1 U2.10 | length 3.8
  Top Layer w0.254: U2.10 92.013,63.861 92.964,62.91 H9.1
ESP_RX: H1.4 U1.13 U2.12 | length 38.5
  Top Layer w0.254: U1.13 76.625,75.247 77.932,76.554 77.932,76.872 79.238,78.179 ; H1.4 82.296,85.09 82.296,82.677 79.238,79.619 79.238,78.179 ; U2.12 95.013,65.261 88.462,71.812 88.462,72.955 82.169,79.248 80.308,79.248 79.238,78.179
ESP_TX: H3.1 U1.12 U2.11 | length 26
  Top Layer w0.254: U1.12 77.811,73.747 H3.1 81.83,77.174 82.592,77.174 84.642,75.124 84.642,73.385 93.19,64.837 93.19,64.484 U2.11
ESP_USBD_N: H11.3 U2.13 | length 18.9
  Top Layer w0.254: U2.13 96.836,63.838 96.836,55.168 97.536,54.468 H11.3
ESP_USBD_P: H11.2 U2.14 | length 19.4
  Top Layer w0.254: U2.14 98.013,63.861 99.289,62.585 99.289,60.439 100.241,59.486 100.241,45.885 H11.2
GND: C1.2 C2.2 C3.2 C4.2 C5.2 C6.2 C7.2 C8.2 C9.2 C10.2 C12.2 C13.2 C14.2 C15.2 C16.2 D2.1 D2.2 D2.3 D3.2 FB5.1 H8.3 H11.1 H12.1 H13.1 J2.1 J3.2 J3.3 j4.A1/B12 j4.B1/A12 pad.1 Q1.2 R1.1 R10.1 R15.1 R21.1 R22.1 R23.1 R24.1 SW1.1 U1.8 U1.23 U1.47 U2.9 U2.19 U3.1 U4.2 U5.3 U5.12 U5.21 | length 5.7
  Top Layer w0.254: U5.12 41.056,71.752 41.056,72.377 41.783,73.104 U5.21 42.033,73.529 U5.3 ; D2.3 D2.2 D2.1
  other v1: 57.658,44.323 43.688,46.101 44.323,48.26 49.149,49.53 88.392,50.8 37.592,51.181 52.197,52.451 80.01,54.229 94.107,54.229 58.166,54.991 33.147,58.039 52.578,59.436 37.973,60.071 29.083,60.579 73.406,62.357 88.392,62.865 34.671,62.992 73.787,64.897 28.194,66.421 36.322,69.469 41.656,69.85 31.877,70.485 28.829,70.612 78.867,72.644 73.025,73.406 89.281,74.676 34.163,75.692 65.532,76.454 43.434,76.581 37.592,78.867 73.533,78.867 49.276,79.502 52.959,80.772 63.119,82.169 90.805,82.804 86.233,83.439 37.846,83.82 34.29,84.074 44.069,85.725 97.536,87.757 52.451,88.138 61.595,88.265 45.085,89.789 61.468,90.043 35.052,90.551 79.883,90.551 100.203,90.805 85.979,90.932 28.829,91.567 61.722,91.694 68.707,92.075 61.722,92.71 41.148,93.853 54.483,95.885 45.466,96.012 70.739,97.536 36.576,97.79 100.962,98.247 60.579,98.298 74.041,98.552 87.757,99.695 48.895,99.949 97.79,102.108 55.626,103.124 35.052,104.14 75.184,105.41 90.932,106.172 97.282,106.299
NetC9_1: C9.1 C10.1 FB3.2 H12.3 | length 14.6
  Top Layer w0.254: FB3.2 C10.1 59.687,47.155 C9.1 60.044,47.412 61.43,46.026 61.43,45.478 62.293,44.615 66.967,44.615 H12.3
NetC11_1: C11.1 L1.1 U3.2 | length 6.9
  Top Layer w0.254: L1.1 48.133,53.594 U3.2 48.133,51.255 48.737,51.859 49.429,51.859 50.546,50.742 50.546,50.673 50.889,50.33 C11.1
NetC11_2: C11.2 U3.6 | length 2.3
  Top Layer w0.254: U3.6 49.083,48.436 49.377,48.73 C11.2
NetD1_2: D1.2 J1.1 Q1.3 | length 14.5
  Top Layer w1.143: D1.2 64.099,102.159 J1.1 70.467,101.785 70.467,99.935 70.646,99.756 Q1.3
NetD2_4: D2.4 R8.1 | length 2.5
  Top Layer w0.254: R8.1 72.517,91.668 72.713,91.864 D2.4
NetD2_5: D2.5 R7.1 | length 4.5
  Top Layer w0.254: R7.1 70.523,89.7 70.866,90.043 70.866,91.129 72.701,92.964 D2.5
NetD2_6: D2.6 R6.1 | length 5.9
  Top Layer w0.254: R6.1 69.129,94.399 69.373,94.643 72.122,94.643 72.701,94.064 D2.6
NetD3_1: D3.1 R13.2 | length 2.4
  Top Layer w0.254: R13.2 49.616,60.833 D3.1@49.743,60.96
NetD4_1: D4.1 R16.1 | length 3.9
  Top Layer w0.254: R16.1 45.593,78.724 46.89,77.427 D4.1
NetD4_2: D4.2 U5.20 | length 4.2
  Top Layer w0.254: U5.20 45.692,74.029 46.89,75.227 D4.2
NetD5_1: D5.1 R17.1 | length 4.5
  Top Layer w0.254: R17.1 47.663,80.772 48.006,80.429 48.006,79.613 50.192,77.427 D5.1
NetD5_2: D5.2 U5.19 | length 7.7
  Top Layer w0.254: U5.19 48.494,73.529 50.192,75.227 D5.2
NetFB5_2: FB5.2 j4.0 | length 26.5
  Top Layer w0.254: j4.0@28.103,75.055 28.131,75.055 28.476,74.71 28.476,73.275 29.058,72.693 ; j4.0@28.103,83.695 32.283,83.695 31.783,83.695 29.439,81.351 29.439,74.789 29.058,74.408 29.058,72.693 ; FB5.2 32.283,73.381 32.283,75.055 31.758,75.055 31.037,74.334 31.037,73.098 30.469,72.53 29.221,72.53 29.058,72.693
Netj4_A5: j4.A5 R22.2 | length 5.4
  Top Layer w0.254: j4.A5 33.834,80.625 33.981,80.772 v2(34.036,80.772) ; v2(34.417,82.55) 34.455,82.512 36.106,82.512 R22.2
  Bottom Layer w0.254: v2(34.036,80.772) 34.036,80.899 34.417,81.28 v2(34.417,82.55)
Netj4_B5: j4.B5 R21.2 | length 6.1
  Top Layer w0.254: R21.2 29.845,75.402 32.045,77.602 32.835,77.602 j4.B5
NetQ1_1: Q1.1 R9.1 | length 12.9
  Top Layer w0.762: v2(67.634,97.266) 69.199,97.266 69.42,97.487 69.708,97.487 69.789,97.568 Q1.1 ; v2(69.85,95.377) 69.95,95.377 69.977,95.404 70.612,95.404 72.744,95.404 73.251,94.897 73.734,94.897 74.134,94.497 74.134,94.107 R9.1
  Bottom Layer w0.762: v2(67.634,97.266) 69.523,95.377 v2(69.85,95.377)
NetR1_2: R1.2 U1.44 | length 2.6
  Top Layer w0.254: R1.2 72.263,66.246 72.319,66.303 U1.44
NetR14_1: R14.1 R15.2 U3.4 | length 18.8
  Top Layer w0.254: R15.2 47.183,46.167 U3.4 47.359,47.954 47.359,47.286 49.839,44.806 56.123,44.806 56.286,44.969 56.286,46.141 56.072,46.355 54.926,46.355 53.213,48.068 53.213,48.349 52.87,48.692 R14.1
NetR18_1: R18.1 U5.9 | length 3.5
  Top Layer w0.254: R18.1 37.768,72.898 37.819,72.949 37.857,72.911 39.105,72.911 39.223,73.029 U5.9
PA1: H3.2 U1.11 | length 6.4
  Top Layer w0.254: U1.11 79.851,73.247 H3.2
PA4: H1.3 U1.14 | length 13.6
  Top Layer w0.254: U1.14 73.844,75.272 73.844,75.917 74.509,76.581 76.454,76.581 77.374,77.501 77.374,77.785 78.105,78.516 78.105,78.994 78.455,79.344 78.455,80.137 79.756,81.438 79.756,85.09 H1.3
PA5: H1.2 U1.15 | length 12.7
  Top Layer w0.254: U1.15 73.344,75.272 73.344,75.992 74.442,77.089 76.387,77.089 76.967,77.669 76.967,80.899 77.089,81.021 H1.2
PA8: H7.5 U1.29 | length 8.2
  Top Layer w0.254: H7.5 59.403,71.722 67.294,71.722 U1.29
PA11: H5.1 U1.32 | length 8.8
  Top Layer w0.254: H5.1 60.076,69.474 63.427,69.474 64.2,70.247 U1.32
PA12: H5.2 U1.33 | length 9.7
  Top Layer w0.254: H5.2 61.364,66.04 65.071,69.747 U1.33
PA15: H6.1 U1.38 | length 10.1
  Top Layer w0.254: H6.1 65.405,60.679 69.319,64.593 U1.38
PB2: H4.3 U1.20 | length 11.7
  Top Layer w0.254: H4.3 66.548,80.899 70.819,76.628 U1.20
PB3: H6.2 U1.39 | length 9.2
  Top Layer w0.254: H6.2 67.945,61.55 69.819,63.424 U1.39
PB4: H6.3 U1.40 | length 8.6
  Top Layer w0.254: U1.40 70.319,65.288 70.256,65.226 70.256,61.444 70.319,61.382 70.319,58.459 H6.3
PB5: H6.4 U1.41 | length 9.9
  Top Layer w0.254: U1.41 70.819,65.214 70.663,65.057 70.663,61.612 70.819,61.456 70.819,59.864 72.123,58.56 72.758,58.56 H6.4
PB6: H6.5 U1.42 | length 11.9
  Top Layer w0.254: U1.42 71.319,65.139 71.069,64.889 71.069,61.781 71.319,61.531 71.319,60.122 71.624,59.817 74.183,59.817 75.565,58.435 H6.5
PB10: H4.2 U1.21 | length 12.6
  Top Layer w0.254: H4.2 64.008,83.758 65.659,82.107 65.659,81.026 70.319,76.366 U1.21
PB11: H4.1 U1.22 | length 13.4
  Top Layer w0.254: H4.1 64.222,82.463 64.239,82.463 64.94,81.762 64.94,81.17 69.819,76.291 U1.22
PB12: H7.1 U1.25 | length 12.3
  Top Layer w0.254: H7.1 59.704,81.139 59.704,80.236 59.704,80.161 59.963,79.902 cw(c59.182,79.121) 60.287,79.106 60.287,79.032 62.09,77.128 62.253,76.965 65.572,73.747 65.677,73.747 U1.25
PB13: H7.2 U1.26 | length 10.6
  Top Layer w0.254: H7.2 65.056,73.247 U1.26
PB14: H7.3 U1.27 | length 9.7
  Top Layer w0.254: H7.3 63.016,72.747 U1.27
PB15: H7.4 U1.28 | length 8.9
  Top Layer w0.254: H7.4 60.976,72.247 U1.28
PC13: H2.5 U1.2 | length 10
  Top Layer w0.254: U1.2 75.844,68.722 76.489,68.722 77.978,67.232 77.978,65.913 80.01,63.881 80.01,62.738 80.554,62.194 81.316,62.194 H2.5
PC14: H2.4 U1.3 | length 7.7
  Top Layer w0.254: U1.3 76.803,69.247 H2.4
PC15: H2.3 U1.4 | length 6.8
  Top Layer w0.254: U1.4 77.364,69.747 80.055,67.056 H2.3
PF0: H2.2 U1.5 | length 6
  Top Layer w0.254: U1.5 77.498,70.247 77.514,70.231 77.934,70.231 77.95,70.247 78.384,70.247 79.035,69.596 H2.2
PF1: H2.1 U1.6 | length 6.9
  Top Layer w0.254: U1.6 75.823,70.743 77.72,70.743 v2(77.724,70.739) ; v2(77.724,71.755) 77.763,71.794 81.192,71.794 H2.1
  Bottom Layer w0.254: v2(77.724,70.739) v2(77.724,71.755)
PF6: H5.3 U1.35 | length 10.3
  Top Layer w0.254: H5.3 60.594,63.5 65.841,68.747 U1.35
PF7: H5.4 U1.36 | length 11.2
  Top Layer w0.254: H5.4 66.469,68.247 U1.36
R\S\T\: H8.1 U1.7 | length 36.7
  Top Layer w0.254: U1.7 80.619,71.247 80.835,71.031 82.385,71.031 83.058,70.358 83.058,60.706 93.472,50.292 93.472,45.974 H8.1
SCL_OLED: H13.3 R11.1 U1.45 | length 24.7
  Top Layer w0.254: U1.45 72.819,65.79 72.771,65.742 72.771,65 73.05,64.721 73.05,64.237 73.406,63.881 73.406,63.5 77.47,59.436 77.47,54.737 74.019,51.286 74.019,50.727 R11.1 ; R11.1@73.838,50.508 74.137,50.209 74.137,49.806 74.422,49.521 H13.3
SDA_OLED: H13.4 R12.1 U1.43 | length 26.9
  Top Layer w0.254: U1.43 71.819,65.064 71.476,64.721 71.476,61.949 73.075,60.35 75.071,60.35 76.67,58.751 76.67,55.461 72.733,51.524 72.733,50.695 72.584,50.546 R12.1 H13.4
SYS_SWCLCK: H8.4 U1.37 | length 41.7
  Top Layer w0.254: U1.37 68.819,66.303 63.5,60.984 63.5,57.531 66.929,54.102 71.27,54.102 72.032,54.864 v2(74.422,54.864) ; v2(76.962,52.324) 76.923,52.285 76.923,51.739 76.581,51.396 76.581,51.142 83.108,44.615 84.024,44.615 84.113,44.704 85.09,44.704 H8.4
  Bottom Layer w0.254: v2(74.422,54.864) v2(76.962,52.324)
SYS_SWDIO: H8.2 U1.34 | length 36.9
  Top Layer w0.254: U1.34 73.093,69.247 v2(74.23,68.111) ; v2(75.057,66.04) 75.184,66.04 91.186,50.038 H8.2
  Bottom Layer w0.254: v2(74.23,68.111) 75.057,67.283 v2(75.057,66.04)
T3C1_MOTOR_PWM: R9.2 R10.2 U1.16 | length 20.5
  Top Layer w0.254: U1.16 72.819,76.225 74.445,77.851 75.67,77.851 75.819,78 75.819,80.391 75.669,80.541 75.199,80.541 74.949,80.791 R10.2 ; R10.2@74.968,80.81 75.311,81.153 75.311,84.175 75.654,84.518 75.654,86.83 76.454,87.63 R9.2
T3C2_R_LED: H1.1 R8.2 U1.17 | length 14.6
  Top Layer w0.254: U1.17 72.319,82.987 H1.1 74.231,85.534 74.231,86.423 72.555,88.1 R8.2
T3C3_G_LED: H4.5 R7.2 U1.18 | length 13.4
  Top Layer w0.254: R7.2 70.485,86.36 H4.5 71.794,85.051 71.794,75.272 U1.18
T3C4_B_LED: H4.4 R6.2 U1.19 | length 19.2
  Top Layer w0.254: R6.2 67.437,91.567 69.088,89.916 H4.4 71.319,82.986 U1.19
USB_D_N: j4.A7 j4.B7 U4.1 | length 6.5
  Top Layer w0.254: j4.B7 32.881,80.102 33.457,80.102 33.712,79.847 33.712,79.403 33.457,79.148 32.881,79.148 j4.A7 33.457,79.125 33.528,79.125 34.417,79.125 34.417,78.986 35.179,78.986 35.179,79.129 35.994,79.944 U4.1
USB_D_P: j4.A6 j4.B6 U4.3 | length 6.2
  Top Layer w0.254: j4.A6@33.003,79.602 32.258,79.602 32.003,79.347 32.003,78.903 32.327,78.579 35.439,78.579 35.975,78.044 U4.3
USB_DETECT: R20.1 R24.2 U5.8 | length 6.9
  Top Layer w0.254: R24.2@36.741,71.247 36.563,71.425 36.563,71.913 36.327,72.149 36.206,72.149 36.043,72.312 36.043,73.484 36.219,73.66 39.491,73.66 39.599,73.552 40.21,73.552 U5.8
USB_RX: U1.31 U5.18 | length 26.6
  Top Layer w0.254: U5.18 43.356,73.006 43.732,73.006 43.78,72.958 43.855,72.958 44.062,72.751 44.062,70.545 44.211,70.396 61.76,70.396 v2(62.23,70.866) ; v2(63.754,70.739) 63.758,70.743 67.315,70.743 U1.31
  Bottom Layer w0.254: v2(62.23,70.866) 63.627,70.866 v2(63.754,70.739)
USB_TX: U1.30 U5.17 | length 27.1
  Top Layer w0.254: U5.17 43.439,72.529 43.462,72.506 43.462,71.763 43.333,71.634 43.333,70.138 43.482,69.99 62.074,69.99 63.331,71.247 U1.30
VUSB: C14.1 FB3.1 j4.A4/B9 j4.B4/A9 R20.2 U3.3 U3.5 U4.5 | length 65.4
  Top Layer w0.686: j4.A4/B9 34.518,81.775 34.788,81.506 34.788,81.153 34.788,80.13
  Top Layer w0.762: 33.706,77.038 34.112,77.038 v2(34.544,77.47) ; v2(34.788,79.672) 34.788,80.13 ; 34.788,81.153 35.479,81.153 35.593,81.039 39.658,81.039 40.302,80.395 40.302,79.493 39.859,79.05 39.175,79.05 U4.5 ; v2(37.338,66.548) 43.815,60.071 43.815,52.235 44.958,51.092 44.996,51.092 C14.1 47.127,51.003 47.183,50.947 U3.3 47.239,50.874 47.239,50.19 48.077,49.352 48.077,48.186 U3.5 48.189,48.074 48.189,47.39 50.024,45.555 FB3.1 ; v2(37.592,69.723) 38.354,70.485 38.354,71.971 38.443,72.06 38.519,72.06 39.459,71.12 v2(39.751,71.12) ; 39.859,78.938 40.748,78.049 40.748,77.674 v2(41.637,76.785)
  Bottom Layer w0.762: v2(34.544,77.47) 34.788,77.714 v2(34.788,79.672) ; v2(37.338,66.548) 37.211,66.675 37.211,69.342 v2(37.592,69.723) ; v2(39.751,71.12) 39.751,74.93 41.402,76.581 41.433,76.581 v2(41.637,76.785)
WAKE_UP: R19.1 R23.2 U5.13 | length 13
  Top Layer w0.254: R19.1 35.014,72.949 34.176,72.111 34.176,70.623 36.092,68.707 36.912,68.707 36.937,68.682 37.485,68.682 37.51,68.707 R23.2 39.235,69.029 39.6,69.029 39.763,69.193 39.763,69.33 40.054,69.621 40.682,69.621 41.51,70.449 41.51,71.706 U5.13
pads on no net: j4. j4.A8 j4.B8 U5.1 U5.2 U5.10 U5.11 U5.14 U5.15 U5.16

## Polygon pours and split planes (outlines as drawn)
GND on Bottom Layer "GND_BOT" (solid, remove dead copper, pour order 2): 37.846,43.688 25.4,56.134 25.4,109.093 98.171,109.093 101.727,105.537 105.41,101.854 105.41,43.688
GND on Top Layer "GND_TOP" (solid, remove dead copper, pour order 1): 37.846,43.688 25.4,56.134 25.4,109.093 98.171,109.093 101.727,105.537 105.41,101.854 105.41,43.688

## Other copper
Top Layer:
  rectangle net VUSB: 32.258,76.708 34.112,77.216
Multi-Layer:
  pour cut-out: 45.563,58.846 51.063,58.846 51.063,52.846 45.563,52.846

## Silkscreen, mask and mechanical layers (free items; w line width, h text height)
Top Overlay:
  drawing of 1258 lines, arcs and shapes, not listed
  text "GND" at 65.786,99.822 h0.76
  text "12V" at 72.009,99.822 h0.76
  text "GND" at 77.343,99.822 h0.76
  text "ANEMO" at 81.407,99.822 h0.76
  text "BOOT" at 91.821,96.266 h0.76
  text "POWER JACK / 12V" at 28.448,94.996 h0.76
  text "9" at 90.932,86.864 h0.76
  text "8" at 93.599,86.864 h0.76
  text "7" at 96.235,86.864 h0.76
  text "6" at 98.679,86.864 h0.76
  text "5" at 101.219,86.864 h0.76
  text "4" at 103.632,86.864 h0.76
  text "USBC" at 29.464,84.709 h0.76
  text "IO PINS" at 88.138,84.391 h0.76 r270
  text "PB11" at 60.96,83.883 h0.76 r270
  text "PB10" at 63.548,83.883 h0.76 r270
  text "PB2" at 66.135,83.883 h0.76 r270
  text "BLUE" at 68.723,83.883 h0.76 r270
  text "GREEN" at 71.311,83.883 h0.76 r270
  text "RED" at 73.898,83.883 h0.76 r270
  text "PA5" at 76.486,83.883 h0.76 r270
  text "PA4" at 79.073,83.883 h0.76 r270
  text "ESPRX" at 81.534,83.883 h0.76 r270
  text "PB12" at 54.864,81.153 h0.76
  text "PB13" at 54.864,78.486 h0.76
  text "ESPTX" at 83.185,76.962 h0.76
  text "PB14" at 54.864,75.819 h0.76
  text "PA1" at 83.185,74.295 h0.76
  text "PB15" at 54.864,73.279 h0.76
  text "UART" at 47.117,72.771 h0.76
  text "PF1" at 83.185,71.628 h0.76
  text "PA8" at 55.499,70.866 h0.76
  text "PF0" at 83.185,68.961 h0.76
  text "PA11" at 55.118,68.072 h0.76
  text "PC15" at 83.185,66.548 h0.76
  text "PA12" at 54.864,65.278 h0.76
  text "PC14" at 83.185,64.008 h0.76
  text "POWER" at 49.149,63.5 h0.76
  text "PF6" at 55.499,62.738 h0.76
  text "PC13" at 83.185,61.468 h0.76
  text "PF7" at 55.499,60.198 h0.76
  text "IO PINS" at 89.535,59.626 h0.76 r270
  text "10" at 92.329,58.293 h0.76
  text "3" at 95.123,58.293 h0.76
  text "2" at 97.663,58.293 h0.76
  text "1" at 100.33,58.293 h0.76
  text "0" at 102.743,58.293 h0.76
  text "PA15" at 64.897,56.642 h0.76 r270
  text "PB3" at 67.564,56.642 h0.76 r270
  text "PB4" at 70.104,56.642 h0.76 r270
  text "PB5" at 72.644,56.642 h0.76 r270
  text "PB6" at 75.184,56.642 h0.76 r270
  text "DCDC" at 39.751,55.372 h0.76
  text "MCU PROGRAMMER" at 84.963,51.943 h0.76
  text "SWCLCK" at 85.471,51.689 h0.76 r270
  text "SWDIO" at 90.678,50.8 h0.76 r270
  text "DHT11" at 64.897,50.609 h0.76 r270
  text "OLED" at 76.2,50.292 h0.76
  text "GND" at 62.357,49.466 h0.76 r270
  text "SDA" at 71.374,49.466 h0.76 r270
  text "SCL" at 74.01,49.466 h0.76 r270
  text "3V3" at 76.327,49.466 h0.76 r270
  text "GND" at 78.867,49.466 h0.76 r270
  text "3V3" at 82.931,49.466 h0.76 r270
  text "GND" at 88.011,49.466 h0.76 r270
  text "RST" at 92.837,49.466 h0.76 r270
  text "GND" at 101.981,49.466 h0.76 r270
  text "ESP USBD" at 98.806,49.276 h0.76
  text "5V" at 67.564,48.832 h0.76 r270
  text "D-" at 96.901,48.832 h0.76 r270
  text "D+" at 99.695,48.832 h0.76 r270
Board Shape:
  the board outline again, w0.254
